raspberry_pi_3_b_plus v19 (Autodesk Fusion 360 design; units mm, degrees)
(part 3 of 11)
sketch "Sketch2" plane through (0, 0, 0) normal (0, 1, 0) x axis (1, 0, 0)
  line L1 (3.725, -2.25) -> (3.725, 1.52)
  line L2 (-5.215, -2.25) -> (3.725, -2.25)
  line L3 (-5.215, 1.52) -> (-5.215, -2.25)
  line L4 (3.325, 1.92) -> (-4.815, 1.92)
  line L5 (-0.745, 5.7) -> (-0.745, -5.7)
  line L6 (5.85, -4.7) -> (-5.015, -4.7)
  line L7 (5.85, 5.7) -> (5.85, -4.7)
  line L8 (-5.015, -4.3) -> (-5.015, -4.7)
  line L9 (-5.85, -4) -> (-5.315, -4)
  line L10 (-5.85, 5.7) -> (-5.85, -4)
  line L11 (-4.75, 5.7) -> (-5.85, 5.7)
  line L12 (-4.75, 5.55) -> (-4.75, 5.7)
  line L13 (3.1, 5.55) -> (-4.75, 5.55)
  line L14 (3.1, 5.7) -> (3.1, 5.55)
  line L15 (5.85, 5.7) -> (3.1, 5.7)
  line L16 (3.85, -4.4) -> (5.85, -4.4)
  line L17 (3.85, -4.7) -> (3.85, -4.4)
  line L18 (-5.215, -4.0172) -> (-5.215, -2.25)
  line L19 (-5.215, 5.7) -> (-5.215, 1.52)
  line L20 (-2.715, 4.55) -> (-5.215, 4.55)
  line L21 (-2.715, 5.55) -> (-2.715, 4.55)
  line L22 (3.725, 4.55) -> (3.725, 5.7)
  line L23 (1.225, 4.55) -> (3.725, 4.55)
  line L24 (1.225, 5.55) -> (1.225, 4.55)
  line L25 (4.35, 0) -> (4.35, 5)
  line L26 (4.65, 5) -> (4.65, 0)
  line L27 (4.5, 0) -> (4.5, 5)
  line L28 (5.4375, -2.85) -> (5.4375, -2.25)
  line L29 (5.2375, -2.05) -> (5.0375, -2.05)
  line L30 (4.8375, -2.25) -> (4.8375, -2.85)
  line L31 (5.0375, -3.05) -> (5.2375, -3.05)
  line L32 (3.725, 4.55) -> (3.725, 1.52)
  line L33 (-3.185, 4.9) -> (-3.185, 5.55)
  line L34 (-4.385, 4.8) -> (-3.285, 4.8)
  line L35 (-4.485, 5.55) -> (-4.485, 4.9)
  line L36 (-0.845, 4.8755) -> (-0.845, 5.55)
  line L37 (1.495, 4.9) -> (1.495, 5.55)
  line L38 (2.695, 4.8) -> (1.595, 4.8)
  line L39 (2.795, 5.55) -> (2.795, 4.9)
  arc A1 centre (3.325, 1.52) radius 0.4 between (3.725, 1.52) and (3.325, 1.92)
  arc A2 centre (-4.815, 1.52) radius 0.4 clockwise from (-5.215, 1.52) to (-4.815, 1.92)
  arc A3 centre (-5.315, -4.3) radius 0.3 clockwise from (-5.315, -4) to (-5.015, -4.3)
  arc A4 centre (4.5, 0) radius 0.15 clockwise from (4.65, 0) to (4.35, 0)
  arc A5 centre (4.5, 5) radius 0.15 clockwise from (4.35, 5) to (4.65, 5)
  circle C1 centre (3.225, 4.05) radius 0.25
  circle C2 centre (-4.715, 4.05) radius 0.25
  circle C3 centre (3.105, -4.3) radius 0.15
  circle C4 centre (2.005, -4.3) radius 0.15
  circle C5 centre (0.905, -4.3) radius 0.15
  circle C6 centre (-0.195, -4.3) radius 0.15
  circle C7 centre (-1.295, -4.3) radius 0.15
  circle C8 centre (-2.395, -4.3) radius 0.15
  circle C9 centre (-3.495, -4.3) radius 0.15
  circle C10 centre (-4.595, -4.3) radius 0.15
  circle C11 centre (3.105, -3.5) radius 0.15
  circle C12 centre (2.005, -3.5) radius 0.15
  circle C13 centre (0.905, -3.5) radius 0.15
  circle C14 centre (-0.195, -3.5) radius 0.15
  circle C15 centre (-1.295, -3.5) radius 0.15
  circle C16 centre (-2.395, -3.5) radius 0.15
  circle C17 centre (-3.495, -3.5) radius 0.15
  circle C18 centre (-4.595, -3.5) radius 0.15
  circle C19 centre (3.105, -2.7) radius 0.15
  circle C20 centre (2.005, -2.7) radius 0.15
  circle C21 centre (0.905, -2.7) radius 0.15
  circle C22 centre (-0.195, -2.7) radius 0.15
  circle C23 centre (-1.295, -2.7) radius 0.15
  circle C24 centre (-2.395, -2.7) radius 0.15
  circle C25 centre (-3.495, -2.7) radius 0.15
  circle C26 centre (-4.595, -2.7) radius 0.15
  arc A6 centre (5.2375, -2.25) radius 0.2 clockwise from (5.2375, -2.05) to (5.4375, -2.25)
  arc A7 centre (5.0375, -2.25) radius 0.2 clockwise from (4.8375, -2.25) to (5.0375, -2.05)
  arc A8 centre (5.0375, -2.85) radius 0.2 clockwise from (5.0375, -3.05) to (4.8375, -2.85)
  arc A9 centre (5.2375, -2.85) radius 0.2 clockwise from (5.4375, -2.85) to (5.2375, -3.05)
  circle C27 centre (-0.745, 4.3) radius 0.375
  arc A10 centre (-3.285, 4.9) radius 0.1 clockwise from (-3.185, 4.9) to (-3.285, 4.8)
  arc A11 centre (-4.385, 4.9) radius 0.1 clockwise from (-4.385, 4.8) to (-4.485, 4.9)
  arc A12 centre (1.595, 4.9) radius 0.1 clockwise from (1.595, 4.8) to (1.495, 4.9)
  arc A13 centre (2.695, 4.9) radius 0.1 clockwise from (2.795, 4.9) to (2.695, 4.8)
  point P11 (-0.745, -2.25)
  point P20 (-5.85, 5.7)
  point P21 (-5.85, 5.7)
  point P26 (5.85, -4.4)
  point P28 (3.85, -4.7)
  point P29 (-5.215, -4.0172)
  point P30 (-5.215, 5.7)
  point P31 (-5.215, 4.55)
  point P33 (-2.715, 5.55)
  point P34 (3.725, 5.7)
  point P37 (1.225, 5.55)
  point P1 (0, 0)
  point P43 (4.5, 0)
  point P90 (-0.745, 4.3)
  point P91 (-3.185, 5.55)
  point P98 (-4.485, 5.55)
  point P99 (-0.845, 5.55)
  point P101 (1.495, 5.55)
  point P92 (-3.185, 4.9)
  point P102 (1.495, 4.9)
  point P93 (-3.285, 4.8)
  point P104 (1.595, 4.8)
  point P95 (-4.385, 4.8)
  point P105 (2.695, 4.8)
  point P96 (-4.485, 4.9)
  point P107 (2.795, 4.9)
  point P108 (2.795, 5.55)
  point P15 (5.85, 5.7)
  point P25 (3.1, 5.7)
  point P22 (-4.75, 5.7)
  point P42 (4.5, 5)
  point P44 (3.225, 4.05)
  point P45 (-4.715, 4.05)
  point P46 (3.105, -4.3)
  vertical L1
  coincident L5 P11
  tangent A1 L4
  horizontal L2
  vertical L3
  tangent A1 L1
  tangent L4 A2
  tangent L3 A2
  equal A1 A2
  horizontal L4
  midpoint L2 P11
  tangent L8 A3
  horizontal L6
  vertical L7
  horizontal L9
  vertical L8
  vertical L10
  horizontal L13
  horizontal L11
  horizontal L15
  coincident P20 P21
  vertical L12
  vertical L14
  tangent A3 L9
  collinear L11 L15
  coincident L7 P26
  coincident L6 P28
  horizontal L16
  vertical L17
  coincident A3 P29
  perpendicular L9 L18
  coincident L11 P30
  vertical L19
  coincident L19 P31
  coincident L13 P33
  horizontal L20
  vertical L21
  coincident L15 P34
  coincident L13 P37
  vertical L22
  horizontal L23
  vertical L24
  collinear L20 L23
  symmetric L5 L21 L24
  tangent L25 A4
  tangent A4 L26
  parallel L25 L26
  tangent L26 A5
  tangent L25 A5
  vertical L27
  horizontal P1 P43
  symmetric L5 C1 C2
  coincident L5 P90
  coincident L13 P91
  tangent L33 A10
  tangent L34 A11
  coincident L13 P98
  tangent A10 L34
  tangent A11 L35
  vertical L33
  horizontal L34
  vertical L35
  equal A10 A11
  coincident L13 P99
  vertical L36
  symmetric P91 L36 P101
  symmetric P92 L36 P102
  symmetric P93 L36 P104
  symmetric A10 L36 A12
  symmetric P95 L36 P105
  symmetric P96 L36 P107
  symmetric A11 L36 A13
  symmetric P98 L36 P108
  dimension "d199" radius A1 = 0.4
  dimension "d203_1" distance P1 L2 = 2.25 (= "sdc_length / 2 - 1 mm - 2.45 mm")
  dimension "d204_1" distance L1 L3 = 8.94
  dimension "d205" distance L2 L4 = 4.17
  dimension "d206_1" distance P1 L6 = 4.7 (= "sdc_length / 2 - 1 mm")
  dimension "d207" distance L7 L10 = 11.7 (= "sdc_width - sdc_shell_thickness * 2")
  dimension "d208_1" distance P1 L10 = 5.85 (= "sdc_width / 2 - sdc_shell_thickness")
  dimension "d209_1" distance L6 L9 = 0.7
  dimension "d210_1" radius A3 = 0.3
  dimension "d212_1" distance L8 L10 = 0.835
  dimension "d213_1" distance P15 P25 = 2.75
  dimension "d214_1" distance P20 P22 = 1.1
  dimension "d215_1" distance P1 L11 = 5.7 (= "sdc_length / 2")
  dimension "d216" distance L11 L13 = 0.15 (= "sdc_shell_thickness")
  dimension "d217" distance L6 L16 = 0.3 (= "sdc_shell_thickness * 2")
  dimension "d218_1" distance L7 L17 = 2
  dimension "d219" distance L19 L21 = 2.5
  dimension "d220" distance L22 L24 = 2.5 (= "d219")
  dimension "d221" distance L13 L23 = 1
  dimension "d222" distance P42 P43 = 5
  dimension "d223_1" radius A4 = 0.15
  dimension "d224" distance P1 L27 = 4.5
  dimension "d225_1" diameter C1 = 0.5
  dimension "d226" distance L22 P44 = 0.5
  dimension "d227_1" distance L20 P45 = 0.5
  dimension "d228_1" diameter C3 = 0.3
  dimension "d229_1" distance L6 P46 = 0.4
  dimension "d236_1" distance P1 P46 = 3.105
  dimension "d237_1" diameter C27 = 0.75
  dimension "d238_1" distance L13 P90 = 1.25
  dimension "d298" distance L13 L34 = 0.75
  dimension "d299" distance L33 L35 = 1.3
  dimension "d300" radius A11 = 0.1
  dimension "d302" distance L5 L33 = 2.44
  dimension "d303" distance L5 L36 = 0.1
  dimension "d234_1" R-Pattern1-uDistance = -1.1
  dimension "d235_1" R-Pattern1-vDistance = 0.8
extrude "Extrude3" new body sketch "Sketch2" profile of A1 L1 L2 L3 L4 A2 L6 L7 L8 A3 L9 L10 L11 L12 L13 L14 L15 L16 L17 L18 L19 L20 L21 L22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 along normal blind 1.27 (= "sdc_height - sdc_shell_thickness") named "d239_1"
sketch "Sketch1" plane through (0, 0, 4.7) normal (0, 0, 1) x axis (1, 0, 0)
  line L1 (5.85, 0) -> (-5.85, 0)
  line L2 (5.85, 1.27) -> (5.85, 0)
  line L3 (3.85, 0.62) -> (5.5, 0.62)
  line L4 (-5.85, 0) -> (-5.85, 1.27)
  line L5 (-5.015, 0.42) -> (3.65, 0.42)
  line L6 (5.5, 0.62) -> (5.5, 1.27)
  line L7 (-5.64, 1.27) -> (-5.64, 0.62)
  line L8 (-5.64, 0.62) -> (-5.015, 0.62)
  line L9 (0, 2.329) -> (0, 0)
  line L10 (2.935, 0.22) -> (2.935, 0.42)
  line L11 (3.275, 0.22) -> (2.935, 0.22)
  line L12 (3.275, 0.42) -> (3.275, 0.22)
  line L13 (2.175, 0.42) -> (2.175, 0.22)
  line L14 (2.175, 0.22) -> (1.835, 0.22)
  line L15 (1.835, 0.22) -> (1.835, 0.42)
  line L16 (1.075, 0.42) -> (1.075, 0.22)
  line L17 (1.075, 0.22) -> (0.735, 0.22)
  line L18 (0.735, 0.22) -> (0.735, 0.42)
  line L19 (-0.025, 0.42) -> (-0.025, 0.22)
  line L20 (-0.025, 0.22) -> (-0.365, 0.22)
  line L21 (-0.365, 0.22) -> (-0.365, 0.42)
  line L22 (-1.125, 0.42) -> (-1.125, 0.22)
  line L23 (-1.125, 0.22) -> (-1.465, 0.22)
  line L24 (-1.465, 0.22) -> (-1.465, 0.42)
  line L25 (-2.225, 0.42) -> (-2.225, 0.22)
  line L26 (-2.225, 0.22) -> (-2.565, 0.22)
  line L27 (-2.565, 0.22) -> (-2.565, 0.42)
  line L28 (-3.325, 0.42) -> (-3.325, 0.22)
  line L29 (-3.325, 0.22) -> (-3.665, 0.22)
  line L30 (-3.665, 0.22) -> (-3.665, 0.42)
  line L31 (-4.425, 0.42) -> (-4.425, 0.22)
  line L32 (-4.425, 0.22) -> (-4.765, 0.22)
  line L33 (-4.765, 0.22) -> (-4.765, 0.42)
  line L34 (3.85, 0) -> (-5.015, 0)
  line L35 (3.85, 1.27) -> (3.85, 0)
  line L36 (-5.015, 1.27) -> (3.85, 1.27)
  line L37 (-5.015, 0) -> (-5.015, 1.27)
  line L38 (5.85, 1.27) -> (3.85, 1.27)
  line L39 (-5.015, 1.27) -> (-5.315, 1.27)
  line L40 (-5.315, 1.27) -> (-5.85, 1.27)
  line L41 (-5.1211, 0.62) -> (-5.015, 0.5139)
  arc A1 centre (3.65, 0.62) radius 0.2 between (3.65, 0.42) and (3.85, 0.62)
  point P11 (-5.85, 0)
  point P18 (-5.85, 0)
  point P8 (3.65, 0.42)
  point P15 (3.65, 0.42)
  point P3 (3.85, 0.62)
  point P12 (3.85, 0.62)
  point P2 (5.5, 0.62)
  point P4 (5.5, 0.62)
  point P14 (5.85, 0)
  point P17 (5.85, 0)
  point P10 (3.65, 0.62)
  point P1 (0, 0)
  point P20 (0, 0)
  point P22 (2.935, 0.42)
  point P25 (3.275, 0.42)
  point P26 (3.105, 0.22)
  point P9 (-5.015, 0.62)
  point P7 (-5.015, 0.42)
  point P6 (-5.64, 1.27)
  point P5 (5.5, 1.27)
  point P16 (5.85, 1.27)
  point P19 (-5.85, 1.27)
  point P64 (-5.015, 0.5139)
  point P65 (-5.1211, 0.62)
  coincident P11 P18
  coincident P8 P15
  coincident P3 P12
  coincident P2 P4
  coincident P14 P17
  vertical L2
  vertical L6
  horizontal L1
  horizontal L3
  horizontal L5
  horizontal L8
  vertical L7
  vertical L4
  tangent A1 L5
  horizontal P10 P12
  collinear L3 L8
  midpoint P1 L1
  coincident P1 P20
  vertical L9
  coincident L5 P22
  perpendicular L5 L10
  perpendicular L10 L11
  coincident L5 P25
  perpendicular L5 L12
  midpoint L11 P26
  coincident P3 L35
  coincident P9 L37
  coincident P7 L37
  coincident P6 L40
  coincident P5 L38
  coincident P16 L38
  coincident P19 L40
  coincident L37 P64
  coincident L8 P65
  dimension "d165_1" distance L2 L6 = 0.35
  dimension "d169" distance L1 L3 = 0.62
  dimension "d170_1" distance L2 L4 = 11.7 (= "sdc_width - sdc_shell_thickness * 2")
  dimension "d187" distance L10 L12 = 0.34
  dimension "d188" distance L6 L7 = 11.14
  dimension "d189" distance L9 P26 = 3.105
  dimension "d190" distance L5 L11 = 0.2
  dimension "d191" distance L5 L8 = 0.2
  dimension "d243_1" angle L8 L41 = 45
  dimension "d244_1" distance P9 L41 = 0.075
  dimension "d194" R-Pattern1-uDistance = -1.1
  dimension "d195_1" R-Pattern1-vDistance = 0
extrude "Extrude4" cut sketch "Sketch1" profile of A1 L3 L5 L6 L7 L8 L35 L36 L37 L38 L39 L40 L41 against normal blind 7.4 named "d241_1"
extrude "Extrude5" cut sketch "Sketch2" profile of A1 L4 A2 L13 L19 L20 L21 L23 L24 C1 C2 C27 L32 along normal blind 0.1 named "d245_1"
extrude "Extrude6" cut sketch "Sketch2" profile of L11 L12 L13 L14 L15 L19 L20 L21 L22 L23 L24 along normal blind 0.15 named "d247_1"
extrude "Extrude7" cut sketch "Sketch2" profile of C27 along normal blind 0.2
sketch "Sketch1" plane through (0, 0.42, 0) normal (0, 1, 0) x axis (-1, 0, 0)
  line L1 (5.015, 2.25) -> (-3.65, 2.25)
  line L2 (5.015, 4.3) -> (5.015, 2.25)
  line L3 (5.015, 4.7) -> (5.015, 4.3)
  line L4 (-3.65, 4.7) -> (5.015, 4.7)
  line L5 (-3.65, 2.25) -> (-3.65, 4.7)
  line L6 (-3.275, 3.7) -> (-3.275, 4.7)
  line L7 (-3.48, 3.7) -> (-3.275, 3.7)
  line L8 (-3.48, 2.25) -> (-3.48, 3.7)
  line L9 (-3.105, 1.8992) -> (-3.105, 4.9008)
  line L10 (-2.935, 3.7) -> (-2.935, 4.7)
  line L11 (-2.73, 3.7) -> (-2.935, 3.7)
  line L12 (-2.73, 2.25) -> (-2.73, 3.7)
  line L13 (-2.175, 3.7) -> (-2.175, 4.7)
  line L14 (-2.38, 3.7) -> (-2.175, 3.7)
  line L15 (-2.38, 2.25) -> (-2.38, 3.7)
  line L16 (-1.835, 3.7) -> (-1.835, 4.7)
  line L17 (-1.63, 3.7) -> (-1.835, 3.7)
  line L18 (-1.63, 2.25) -> (-1.63, 3.7)
  line L19 (-1.075, 3.7) -> (-1.075, 4.7)
  line L20 (-1.28, 3.7) -> (-1.075, 3.7)
  line L21 (-1.28, 2.25) -> (-1.28, 3.7)
  line L22 (-0.735, 3.7) -> (-0.735, 4.7)
  line L23 (-0.53, 3.7) -> (-0.735, 3.7)
  line L24 (-0.53, 2.25) -> (-0.53, 3.7)
  line L25 (0.025, 3.7) -> (0.025, 4.7)
  line L26 (-0.18, 3.7) -> (0.025, 3.7)
  line L27 (-0.18, 2.25) -> (-0.18, 3.7)
  line L28 (0.365, 3.7) -> (0.365, 4.7)
  line L29 (0.57, 3.7) -> (0.365, 3.7)
  line L30 (0.57, 2.25) -> (0.57, 3.7)
  line L31 (1.125, 3.7) -> (1.125, 4.7)
  line L32 (0.92, 3.7) -> (1.125, 3.7)
  line L33 (0.92, 2.25) -> (0.92, 3.7)
  line L34 (1.465, 3.7) -> (1.465, 4.7)
  line L35 (1.67, 3.7) -> (1.465, 3.7)
  line L36 (1.67, 2.25) -> (1.67, 3.7)
  line L37 (2.225, 3.7) -> (2.225, 4.7)
  line L38 (2.02, 3.7) -> (2.225, 3.7)
  line L39 (2.02, 2.25) -> (2.02, 3.7)
  line L40 (2.565, 3.7) -> (2.565, 4.7)
  line L41 (2.77, 3.7) -> (2.565, 3.7)
  line L42 (2.77, 2.25) -> (2.77, 3.7)
  line L43 (3.325, 3.7) -> (3.325, 4.7)
  line L44 (3.12, 3.7) -> (3.325, 3.7)
  line L45 (3.12, 2.25) -> (3.12, 3.7)
  line L46 (3.665, 3.7) -> (3.665, 4.7)
  line L47 (3.87, 3.7) -> (3.665, 3.7)
  line L48 (3.87, 2.25) -> (3.87, 3.7)
  line L49 (4.425, 3.7) -> (4.425, 4.7)
  line L50 (4.22, 3.7) -> (4.425, 3.7)
  line L51 (4.22, 2.25) -> (4.22, 3.7)
  line L52 (4.765, 3.7) -> (4.765, 4.7)
  line L53 (4.97, 3.7) -> (4.765, 3.7)
  line L54 (4.97, 2.25) -> (4.97, 3.7)
  line L55 (-2.935, 4.7) -> (-3.275, 4.7)
  line L56 (-2.73, 2.25) -> (-3.48, 2.25)
  line L57 (-1.63, 2.25) -> (-2.38, 2.25)
  line L58 (-1.835, 4.7) -> (-2.175, 4.7)
  circle C1 centre (3.495, 2.7) radius 0.15
  circle C2 centre (3.495, 3.5) radius 0.15
  circle C3 centre (2.395, 3.5) radius 0.15
  point P10 (-3.275, 4.7)
  point P13 (-3.48, 2.25)
  point P16 (-2.935, 4.7)
  point P11 (-3.275, 3.7)
  point P17 (-2.935, 3.7)
  point P12 (-3.48, 3.7)
  point P18 (-2.73, 3.7)
  point P19 (-2.73, 2.25)
  point P1 (0, 0)
  coincident L4 P10
  perpendicular L6 L7
  coincident L1 P13
  vertical L6
  vertical L8
  vertical L9
  symmetric P10 L9 P16
  symmetric P11 L9 P17
  symmetric P12 L9 P18
  symmetric P13 L9 P19
  dimension "d251_1" distance P1 L9 = 3.105
  dimension "d252_1" distance L6 L10 = 0.34
  dimension "d253_1" distance L8 L12 = 0.75
  dimension "d254_1" distance L4 L7 = 1
  dimension "d257" R-Pattern1-uDistance = 1.1
  dimension "d258_1" R-Pattern1-vDistance = 0
extrude "Extrude8" cut sketch "Sketch1" profile of L1 L4 C1 C2 C3 L6 L7 L8 L10 L11 L12 L13 L14 L15 L16 L17 L18 L19 L20 L21 L22 L23 L24 L25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 against normal blind 0.2 named "d259_1"
face "Face1" sketch "Sketch1"
extrude "Extrude2" add of existing geometry blind 0.2
face "EdgeFlange2" FlangeHeight 0.25 named "d266_1" FlangeAngle 55 named "d267_1" BendRadius 0.1 named "d268_1"
face "EdgeFlange3" FlangeHeight 0.5 named "d269_1" FlangeAngle 55 BendRadius 0.1
face "EdgeFlange4" FlangeHeight 3.2 FlangeAngle 5
step "Unfold1"
sketch "Sketch1" plane through (0, 0.6122, 0.0536) normal (0, 0.9962, 0.0872) x axis (1, 0, 0)
  line L1 (3.48, -2.1961) -> (2.73, -2.1961)
  line L2 (3.48, 0.9864) -> (3.48, -2.1961)
  line L3 (2.73, 0.9864) -> (3.48, 0.9864)
  line L4 (2.73, -2.1961) -> (2.73, 0.9864)
  line L5 (3.105, -0.4) -> (3.105, 0.9864)
  line L6 (3.4757, -2.0648) -> (3.275, 0.9864)
  line L7 (3.48, -3.6493) -> (3.48, -2.2048)
  line L8 (2.7343, -2.0648) -> (2.935, 0.9864)
  arc A1 centre (1.48, -2.1961) radius 2 clockwise from (3.4757, -2.0648) to (3.48, -2.1961)
  arc A2 centre (4.73, -2.1961) radius 2 clockwise from (2.73, -2.1961) to (2.7343, -2.0648)
  point P6 (3.105, 0.9864)
  point P8 (3.275, 0.9864)
  point P3 (3.48, -2.1961)
  point P10 (3.48, -2.1961)
  point P14 (2.935, 0.9864)
  point P9 (3.4757, -2.0648)
  point P15 (2.7343, -2.0648)
  point P17 (2.73, -2.1961)
  midpoint L3 P6
  vertical L5
  coincident L3 P8
  tangent L6 A1
  coincident P3 P10
  tangent A1 L7
  symmetric L5 P8 P14
  symmetric L5 P9 P15
  symmetric L5 P10 P17
  symmetric L5 A1 A2
  dimension "d274" distance P8 P14 = 0.34
  dimension "d275" radius A1 = 2
extrude "Extrude3" cut sketch "Sketch1" profile of L2 L3 L4 L6 A1 L8 A2 no distance stored
step "Refold1"
face "EdgeFlange5" FlangeHeight 1 FlangeAngle 25
face "EdgeFlange6" FlangeHeight 0.6 FlangeAngle 75
step "Unfold2"
sketch "Sketch2" plane through (0, 1.5712, -1.5712) normal (0, 0.7071, -0.7071) x axis (-1, 0, 0)
  line L1 (-3.275, -0.7573) -> (-2.935, -0.7573)
  line L2 (-3.275, -1.0504) -> (-3.275, -0.7573)
  line L3 (-2.935, -1.0504) -> (-3.275, -1.0504)
  line L4 (-2.935, -0.7573) -> (-2.935, -1.0504)
  line L5 (-3.105, -0.2989) -> (-3.105, -1.0504)
  arc A1 centre (-3.055, -0.9504) radius 0.1 clockwise from (-2.9571, -0.9709) to (-3.055, -1.0504)
  arc A2 centre (-3.9769, -0.7573) radius 1.0419 clockwise from (-2.935, -0.7573) to (-2.9571, -0.9709)
  arc A3 centre (-3.155, -0.9504) radius 0.1 clockwise from (-3.155, -1.0504) to (-3.2529, -0.9709)
  arc A4 centre (-2.2331, -0.7573) radius 1.0419 clockwise from (-3.2529, -0.9709) to (-3.275, -0.7573)
  point P6 (-3.105, -1.0504)
  point P8 (-3.055, -1.0504)
  point P2 (-2.935, -0.7573)
  point P11 (-2.935, -0.7573)
  point P14 (-3.155, -1.0504)
  point P9 (-2.9571, -0.9709)
  point P15 (-3.2529, -0.9709)
  point P17 (-3.275, -0.7573)
  midpoint L3 P6
  vertical L5
  tangent L3 A1
  coincident L3 P8
  tangent L4 A2
  coincident P2 P11
  tangent A1 A2
  symmetric L5 P8 P14
  symmetric L5 P9 P15
  symmetric L5 A1 A3
  symmetric L5 P11 P17
  symmetric L5 A2 A4
  dimension "d281" radius A1 = 0.1
  dimension "d282" distance L5 P8 = 0.05
extrude "Extrude4" cut sketch "Sketch2" profile of L2 L3 L4 A1 A2 A3 A4 no distance stored
step "Refold2"
face "Face1" sketch "Sketch1"
extrude "Extrude2" add of existing geometry blind 0.2 named "d264_1"
face "EdgeFlange2" FlangeHeight 0.25 named "d266_1" FlangeAngle 55 named "d267_1" BendRadius 0.1 named "d268_1"
face "EdgeFlange3" FlangeHeight 0.5 named "d269_1" FlangeAngle 55 named "d270_1" BendRadius 0.1 named "d271_1"
face "EdgeFlange4" FlangeHeight 3.5 named "d272_1" FlangeAngle 5 named "d273_1"
step "Unfold1"
sketch "Sketch1" plane through (0, 0.6122, 0.0536) normal (0, 0.9962, 0.0872) x axis (1, 0, 0)
  line L1 (3.48, -2.1961) -> (2.73, -2.1961)
  line L2 (3.48, 1.2864) -> (3.48, -2.1961)
  line L3 (2.73, 1.2864) -> (3.48, 1.2864)
  line L4 (2.73, -2.1961) -> (2.73, 1.2864)
  line L5 (3.105, -0.4) -> (3.105, 1.2864)
  line L6 (3.4764, -2.0765) -> (3.275, 1.2864)
  line L7 (3.48, -3.6493) -> (3.48, -2.2048)
  line L8 (2.7336, -2.0765) -> (2.935, 1.2864)
  arc A1 centre (1.48, -2.1961) radius 2 clockwise from (3.4764, -2.0765) to (3.48, -2.1961)
  arc A2 centre (4.73, -2.1961) radius 2 clockwise from (2.73, -2.1961) to (2.7336, -2.0765)
  point P6 (3.105, 1.2864)
  point P8 (3.275, 1.2864)
  point P3 (3.48, -2.1961)
  point P10 (3.48, -2.1961)
  point P14 (2.935, 1.2864)
  point P9 (3.4764, -2.0765)
  point P15 (2.7336, -2.0765)
  point P17 (2.73, -2.1961)
  midpoint L3 P6
  vertical L5
  coincident L3 P8
  tangent L6 A1
  coincident P3 P10
  tangent A1 L7
  symmetric L5 P8 P14
  symmetric L5 P9 P15
  symmetric L5 P10 P17
  symmetric L5 A1 A2
  dimension "d274_1" distance P8 P14 = 0.34
  dimension "d275_1" radius A1 = 2
extrude "Extrude3" cut sketch "Sketch1" profile of L2 L3 L4 L6 A1 L8 A2 no distance stored
step "Refold1"
face "EdgeFlange5" FlangeHeight 1 named "d277_1" FlangeAngle 25 named "d278_1"
face "EdgeFlange6" FlangeHeight 0.6 named "d279_1" FlangeAngle 75 named "d280_1"
step "Unfold2"
sketch "Sketch2" plane through (0, 1.7337, -1.7337) normal (0, 0.7071, -0.7071) x axis (-1, 0, 0)
  line L1 (-3.275, -0.9502) -> (-2.935, -0.9502)
  line L2 (-3.275, -1.2432) -> (-3.275, -0.9502)
  line L3 (-2.935, -1.2432) -> (-3.275, -1.2432)
  line L4 (-2.935, -0.9502) -> (-2.935, -1.2432)
  line L5 (-3.105, -0.2989) -> (-3.105, -1.2432)
  arc A1 centre (-3.055, -1.1432) radius 0.1 clockwise from (-2.9571, -1.1637) to (-3.055, -1.2432)
  arc A2 centre (-3.9769, -0.9502) radius 1.0419 clockwise from (-2.935, -0.9502) to (-2.9571, -1.1637)
  arc A3 centre (-3.155, -1.1432) radius 0.1 clockwise from (-3.155, -1.2432) to (-3.2529, -1.1637)
  arc A4 centre (-2.2331, -0.9502) radius 1.0419 clockwise from (-3.2529, -1.1637) to (-3.275, -0.9502)
  point P6 (-3.105, -1.2432)
  point P8 (-3.055, -1.2432)
  point P2 (-2.935, -0.9502)
  point P11 (-2.935, -0.9502)
  point P14 (-3.155, -1.2432)
  point P9 (-2.9571, -1.1637)
  point P15 (-3.2529, -1.1637)
  point P17 (-3.275, -0.9502)
  midpoint L3 P6
  vertical L5
  tangent L3 A1
  coincident L3 P8
  tangent L4 A2
  coincident P2 P11
  tangent A1 A2
  symmetric L5 P8 P14
  symmetric L5 P9 P15
  symmetric L5 A1 A3
  symmetric L5 P11 P17
  symmetric L5 A2 A4
  dimension "d281_1" radius A1 = 0.1
  dimension "d282_1" distance L5 P8 = 0.05
extrude "Extrude4" cut sketch "Sketch2" profile of L2 L3 L4 A1 A2 A3 A4 no distance stored
step "Refold2"
copy_paste "CopyPaste1"
copy_paste "CopyPaste2"
copy_paste "CopyPaste3"
copy_paste "CopyPaste4"
face "Face1" sketch "Sketch1"
extrude "Extrude2" add of existing geometry blind 0.2 named "d264_2"
face "EdgeFlange2" FlangeHeight 0.25 named "d266_2" FlangeAngle 55 named "d267_2" BendRadius 0.1 named "d268_2"
face "EdgeFlange3" FlangeHeight 0.5 named "d269_2" FlangeAngle 55 named "d270_2" BendRadius 0.1 named "d271_2"
face "EdgeFlange4" FlangeHeight 3.15 named "d272_2" FlangeAngle 5 named "d273_2"
step "Unfold1"
sketch "Sketch1" plane through (0, 0.6122, 0.0536) normal (0, 0.9962, 0.0872) x axis (1, 0, 0)
  line L1 (3.48, -2.1961) -> (2.73, -2.1961)
  line L2 (3.48, 0.9364) -> (3.48, -2.1961)
  line L3 (2.73, 0.9364) -> (3.48, 0.9364)
  line L4 (2.73, -2.1961) -> (2.73, 0.9364)
  line L5 (3.105, -0.4) -> (3.105, 0.9364)
  line L6 (3.4755, -2.0627) -> (3.275, 0.9364)
  line L7 (3.48, -3.6493) -> (3.48, -2.2048)
  line L8 (2.7345, -2.0627) -> (2.935, 0.9364)
  arc A1 centre (1.48, -2.1961) radius 2 clockwise from (3.4755, -2.0627) to (3.48, -2.1961)
  arc A2 centre (4.73, -2.1961) radius 2 clockwise from (2.73, -2.1961) to (2.7345, -2.0627)
  point P6 (3.105, 0.9364)
  point P8 (3.275, 0.9364)
  point P3 (3.48, -2.1961)
  point P10 (3.48, -2.1961)
  point P14 (2.935, 0.9364)
  point P9 (3.4755, -2.0627)
  point P15 (2.7345, -2.0627)
  point P17 (2.73, -2.1961)
  midpoint L3 P6
  vertical L5
  coincident L3 P8
  tangent L6 A1
  coincident P3 P10
  tangent A1 L7
  symmetric L5 P8 P14
  symmetric L5 P9 P15
  symmetric L5 P10 P17
  symmetric L5 A1 A2
  dimension "d274_2" distance P8 P14 = 0.34
  dimension "d275_2" radius A1 = 2
extrude "Extrude3" cut sketch "Sketch1" profile of L2 L3 L4 L6 A1 L8 A2 no distance stored
step "Refold1"
face "EdgeFlange5" FlangeHeight 1 named "d277_2" FlangeAngle 25 named "d278_2"
face "EdgeFlange6" FlangeHeight 0.6 named "d279_2" FlangeAngle 75 named "d280_2"
step "Unfold2"
sketch "Sketch2" plane through (0, 1.5441, -1.5441) normal (0, 0.7071, -0.7071) x axis (-1, 0, 0)
  line L1 (-3.275, -0.7252) -> (-2.935, -0.7252)
  line L2 (-3.275, -1.0183) -> (-3.275, -0.7252)
  line L3 (-2.935, -1.0183) -> (-3.275, -1.0183)
  line L4 (-2.935, -0.7252) -> (-2.935, -1.0183)
  line L5 (-3.105, -0.2989) -> (-3.105, -1.0183)
  arc A1 centre (-3.055, -0.9183) radius 0.1 clockwise from (-2.9571, -0.9388) to (-3.055, -1.0183)
  arc A2 centre (-3.9769, -0.7252) radius 1.0419 clockwise from (-2.935, -0.7252) to (-2.9571, -0.9388)
  arc A3 centre (-3.155, -0.9183) radius 0.1 clockwise from (-3.155, -1.0183) to (-3.2529, -0.9388)
  arc A4 centre (-2.2331, -0.7252) radius 1.0419 clockwise from (-3.2529, -0.9388) to (-3.275, -0.7252)
  point P6 (-3.105, -1.0183)
  point P8 (-3.055, -1.0183)
  point P2 (-2.935, -0.7252)
  point P11 (-2.935, -0.7252)
  point P14 (-3.155, -1.0183)
  point P9 (-2.9571, -0.9388)
  point P15 (-3.2529, -0.9388)
  point P17 (-3.275, -0.7252)
  midpoint L3 P6
  vertical L5
  tangent L3 A1
  coincident L3 P8
  tangent L4 A2
  coincident P2 P11
  tangent A1 A2
  symmetric L5 P8 P14
  symmetric L5 P9 P15
  symmetric L5 A1 A3
  symmetric L5 P11 P17
  symmetric L5 A2 A4
  dimension "d281_2" radius A1 = 0.1
  dimension "d282_2" distance L5 P8 = 0.05
extrude "Extrude4" cut sketch "Sketch2" profile of L2 L3 L4 A1 A2 A3 A4 no distance stored
step "Refold2"
position "Position1"
copy_paste "CopyPaste5"
sketch "Sketch3" plane through (0, 1.27, 0) normal (0, 1, 0) x axis (-1, 0, 0)
  line L1 (-5.5, 4.4) -> (-5.5, -2.7)
  line L2 (-5.85, 4.4) -> (-5.5, 4.4)
  line L3 (-5.85, -5.7) -> (-5.85, 4.4)
  line L4 (-3.1, -5.7) -> (-5.85, -5.7)
  line L5 (-3.1, -5.55) -> (-3.1, -5.7)
  line L6 (-2.795, -5.55) -> (-3.1, -5.55)
  line L7 (4.75, -5.7) -> (4.75, -5.55)
  line L8 (5.85, -5.7) -> (4.75, -5.7)
  line L9 (5.85, 4) -> (5.85, -5.7)
  line L10 (5.64, 4) -> (5.85, 4)
  line L11 (5.64, -2.7) -> (5.64, 4)
  line L12 (-4.35, -2.7) -> (5.64, -2.7)
  line L13 (-4.35, -5) -> (-4.35, -2.7)
  line L14 (-4.65, -2.7) -> (-4.65, -5)
  line L15 (-5.5, -2.7) -> (-4.65, -2.7)
  line L16 (-5.5, -5.2) -> (-5.5, -2.7)
  line L17 (-1.495, -5.2) -> (-5.5, -5.2)
  line L18 (-1.495, -2.7) -> (-1.495, -5.2)
  line L19 (3.185, -5.2) -> (3.185, -2.7)
  line L20 (5.64, -5.2) -> (3.185, -5.2)
  line L21 (5.64, -2.7) -> (5.64, -5.2)
  line L22 (-2.795, -4.9) -> (-2.795, -5.55)
  line L23 (-1.595, -4.8) -> (-2.695, -4.8)
  line L24 (-1.495, -5.55) -> (-1.495, -4.9)
  line L25 (3.185, -5.55) -> (-1.495, -5.55)
  line L26 (3.185, -4.9) -> (3.185, -5.55)
  line L27 (4.385, -4.8) -> (3.285, -4.8)
  line L28 (4.485, -5.55) -> (4.485, -4.9)
  line L29 (4.75, -5.55) -> (4.485, -5.55)
  arc A1 centre (-4.5, -5) radius 0.15 clockwise from (-4.35, -5) to (-4.65, -5)
  circle C1 centre (4.715, -4.05) radius 0.25
  circle C2 centre (-3.225, -4.05) radius 0.25
  arc A2 centre (-2.695, -4.9) radius 0.1 clockwise from (-2.795, -4.9) to (-2.695, -4.8)
  arc A3 centre (-1.595, -4.9) radius 0.1 clockwise from (-1.595, -4.8) to (-1.495, -4.9)
  arc A4 centre (3.285, -4.9) radius 0.1 clockwise from (3.185, -4.9) to (3.285, -4.8)
  arc A5 centre (4.385, -4.9) radius 0.1 clockwise from (4.385, -4.8) to (4.485, -4.9)
  point P2 (-5.5, -2.7)
  point P21 (-5.5, -2.7)
  point P23 (-1.495, -2.7)
  point P24 (3.185, -2.7)
  point P13 (5.64, -2.7)
  point P27 (5.64, -2.7)
  point P25 (3.185, -5.2)
  point P44 (-1.495, -5.2)
  coincident P2 P21
  horizontal L17
  vertical L16
  coincident L12 P23
  vertical L18
  coincident L12 P24
  vertical L19
  horizontal L20
  vertical L21
  coincident P13 P27
  collinear L17 L20
  coincident P25 L26
  coincident L24 P44
  dimension "d286" distance L15 L17 = 2.5
extrude "Extrude9" cut sketch "Sketch3" profile of L12 L13 A1 L14 L15 C1 C2 L16 L17 L18 L19 L20 L21 L22 A4 L27 A5 L28 against normal blind 0.65
sketch "Sketch4" plane through (5.85, 0, 0) normal (1, 0, 0) x axis (0, 0, -1)
  line L1 (5.7, 0) -> (-4.4, 0)
  line L2 (5.7, 1.27) -> (5.7, 0)
  line L3 (-4.4, 1.27) -> (5.7, 1.27)
  line L4 (-4.4, 0) -> (-4.4, 1.27)
  line L5 (3.5625, 0.82) -> (2.4375, 0.82)
  line L6 (3.5625, 0.32) -> (3.5625, 0.82)
  line L7 (2.4375, 0.32) -> (3.5625, 0.32)
  line L8 (2.4375, 0.82) -> (2.4375, 0.32)
  line L9 (2.4375, 0.57) -> (3.5625, 0.57)
  line L10 (1.625, 0.625) -> (1.625, 0)
  line L11 (1.025, 0.725) -> (1.525, 0.725)
  line L12 (0.925, 0) -> (0.925, 0.625)
  line L13 (-3.8, 0.82) -> (-4.4, 0.82)
  line L14 (-3.8, 0.32) -> (-3.8, 0.82)
  line L15 (-4.4, 0.32) -> (-3.8, 0.32)
  line L16 (-4.4, 0.82) -> (-4.4, 0.32)
  arc A1 centre (1.525, 0.625) radius 0.1 clockwise from (1.525, 0.725) to (1.625, 0.625)
  arc A2 centre (1.025, 0.625) radius 0.1 clockwise from (0.925, 0.625) to (1.025, 0.725)
  point P10 (3.5625, 0.57)
  point P11 (2.4375, 0.57)
  point P12 (3, 0.57)
  point P20 (0.925, 0)
  point P13 (1.625, 0)
  point P21 (-4.4, 0.82)
  point P25 (1.275, 0.725)
  point P1 (0, 0)
  horizontal L5
  vertical L6
  horizontal L7
  vertical L8
  midpoint L6 P10
  midpoint L8 P11
  midpoint L9 P12
  tangent L10 A1
  tangent L11 A2
  vertical L12
  coincident L1 P20
  vertical L10
  coincident L1 P13
  tangent A1 L11
  tangent A2 L12
  horizontal L11
  equal A1 A2
  horizontal L13
  vertical L14
  horizontal L15
  vertical L16
  collinear L7 L15
  collinear L5 L13
  coincident L4 P21
  midpoint L11 P25
  dimension "d304" distance L5 L7 = 0.5
  dimension "d305" distance L6 L8 = 1.125
  dimension "d306" distance L3 L9 = 0.7
  dimension "d308" distance L1 L11 = 0.725
  dimension "d309" radius A2 = 0.1
  dimension "d310" distance L10 L12 = 0.7
  dimension "d315" distance L14 L16 = 0.6
  dimension "d325" distance P1 P25 = 1.275
  dimension "d326" distance P1 P12 = 3
extrude "Extrude10" add sketch "Sketch4" profile of L1 L4 L5 L6 L7 L8 L10 A1 L11 A2 L12 L13 L14 L15 L16 along normal blind 0.15 (= "sdc_shell_thickness")
chamfer "Chamfer1" distance 0.15
sketch "Sketch5" plane through (0, 1.27, 0) normal (0, 1, 0) x axis (-1, 0, 0)
  line L1 (-5.5, -5.2) -> (-2.795, -5.2)
  line L2 (-5.5, 4.4) -> (-5.5, -5.2)
  line L3 (-5.85, 4.4) -> (-5.5, 4.4)
  line L4 (-5.85, -5.7) -> (-5.85, 4.4)
  line L5 (-3.1, -5.7) -> (-5.85, -5.7)
  line L6 (-3.1, -5.55) -> (-3.1, -5.7)
  line L7 (-2.795, -5.55) -> (-3.1, -5.55)
  line L8 (-2.795, -5.2) -> (-2.795, -5.55)
  line L9 (-5.55, 3.85) -> (-5.85, 3.85)
  line L10 (-5.55, 4.35) -> (-5.55, 3.85)
  line L11 (-5.85, 4.35) -> (-5.55, 4.35)
  line L12 (5.85, 4) -> (5.85, -5.7)
  line L13 (5.85, -5.7) -> (5.85, 4)
  line L14 (5.65, 3.95) -> (5.85, 3.95)
  line L15 (5.65, 3.45) -> (5.65, 3.95)
  line L16 (5.85, 3.45) -> (5.65, 3.45)
  line L17 (5.64, 4) -> (5.85, 4)
  point P10 (-5.85, 3.85)
  point P13 (-5.85, 4.35)
  point P18 (5.85, 3.95)
  point P21 (5.85, 3.45)
  point P5 (-5.85, 4.4)
  coincident L4 P10
  coincident L4 P13
  horizontal L11
  vertical L10
  horizontal L9
  coincident L12 P18
  coincident L12 P21
  horizontal L16
  vertical L15
  horizontal L14
  dimension "d316" distance P5 L11 = 0.05
  dimension "d317" distance L9 L11 = 0.5
  dimension "d318" distance L4 L10 = 0.3
  dimension "d320" distance L14 L17 = 0.05
  dimension "d321" distance P18 P21 = 0.5
  dimension "d322" distance L13 L15 = 0.2
extrude "Extrude11" add sketch "Sketch5" profile of L4 L9 L10 L11 L12 L13 L14 L15 L16 along normal blind 0.15 (= "sdc_shell_thickness")
work_plane "WorkPlane1" AlongDistance 0.05
sketch "Sketch1" plane through (4.4, 0, 0) normal (1, 0, 0) x axis (0, 0, -1)
  line L1 (0.4, 0.2) -> (4.06, 0.2)
  line L2 (0.4, 1.2) -> (0.4, 0.2)
  line L3 (4.9, 0.6) -> (0.9, 0.6)
  line L4 (4.9, 0.2) -> (4.9, 0.6)
  line L5 (0.9, 1.2) -> (0.4, 1.2)
  line L6 (0.9, 0.7) -> (0.9, 1.2)
  line L7 (4.06, 0.125) -> (4.4, 0.125)
  line L8 (4.06, 0.2) -> (4.06, 0.125)
  line L9 (4.4, 0.2) -> (4.9, 0.2)
  line L10 (4.4, 0.125) -> (4.4, 0.2)
  arc A1 centre (0.9, 0.65) radius 0.05 clockwise from (0.9, 0.6) to (0.9, 0.7)
  point P8 (0.9, 0.7)
  point P9 (0.9, 0.65)
  point P1 (0, 0)
  horizontal L1
  vertical L2
  horizontal L3
  vertical L4
  perpendicular L2 L5
  perpendicular L5 L6
  tangent L3 A1
  perpendicular L4 L7
  perpendicular L1 L8
  vertical P8 P9
  perpendicular L4 L9
  perpendicular L7 L10
  collinear L1 L9
  dimension "d327" distance L1 L3 = 0.4
  dimension "d328" distance L1 L7 = 0.075 (= "sdc_shell_thickness / 2")
  dimension "d329" radius A1 = 0.05
  dimension "d330" distance L5 P8 = 0.5
  dimension "d333" distance L2 L6 = 0.5
  dimension "d334" distance L2 L4 = 4.5
  dimension "d339" distance L4 L10 = 0.5
  dimension "d340" distance L8 L10 = 0.34
  dimension "d345" distance P1 L2 = 0.4
  dimension "d346" distance P1 L1 = 0.2
face "Face1" sketch "Sketch1"
face "EdgeFlange2" FlangeHeight 4 FlangeAngle 15
face "EdgeFlange3" FlangeHeight 1.2 FlangeAngle 135
face "EdgeFlange4" FlangeHeight 0.65 FlangeAngle 90 BendRadius 0.05
work_plane "WorkPlane1" AlongDistance 5 (= "sdc_width / 2 - 1 mm")
sketch "Sketch1" plane through (5, 0, 0) normal (1, 0, 0) x axis (0, 0, -1)
  line L1 (0, 1.25) -> (0, 0.25)
  line L2 (0.65, 1.25) -> (0, 1.25)
  line L3 (0.65, 0.75) -> (0.65, 1.25)
  line L4 (0.6, 0.25) -> (0.6, 0.75)
  line L5 (0.13, 0.2) -> (0.47, 0.2)
  line L6 (0.3, 0.2) -> (0.3, 1.25)
  line L7 (0.47, 0.25) -> (0.47, 0.2)
  line L8 (0.6, 0.25) -> (0.47, 0.25)
  line L9 (0.13, 0.25) -> (0.13, 0.2)
  line L10 (0, 0.25) -> (0.13, 0.25)
  line L11 (0.6, 0.75) -> (0.65, 0.75)
  point P9 (0.3, 0.2)
  point P5 (0.6, 0.75)
  point P10 (0.6, 0.75)
  point P12 (0.6, 0.25)
  point P14 (0, 0.25)
  point P3 (0.65, 1.25)
  point P4 (0.65, 0.75)
  point P1 (0, 0)
  vertical L3
  horizontal L2
  vertical L1
  horizontal L5
  vertical L4
  midpoint L5 P9
  vertical L6
  horizontal L11
  perpendicular L5 L7
  perpendicular L4 L8
  perpendicular L1 L10
  collinear L8 L10
  coincident P5 P10
  symmetric L6 P12 P14
  dimension "d349" distance P3 P4 = 0.5
  dimension "d352" distance P1 L6 = 0.3
  dimension "d353" distance P1 P9 = 0.2
  dimension "d355" distance L5 L10 = 0.05
  dimension "d356" distance L2 L10 = 1
  dimension "d357" distance L7 L9 = 0.34
  dimension "d360" distance L1 L4 = 0.6
  dimension "d361" distance L3 L4 = 0.05
face "Face1" sketch "Sketch1"
face "EdgeFlange2" FlangeHeight 4.25 FlangeAngle 5
face "EdgeFlange3" FlangeHeight 0.8 FlangeAngle 90 BendRadius 0.1 BendRemnant 0.3 EdgeWidth 0.2
work_plane "WorkPlane1" AlongDistance 15.35 named "d2_3"
canvas "Canvas1"
sketch "Sketch1" plane through (0, 0, 15.35) normal (0, 0, 1) x axis (1, 0, 0)
  line L1 (-8.5, -6.55) -> (8.5, -6.55)
  line L2 (8.5, 6.55) -> (-8.5, 6.55)
  line L3 (8.5, -6.55) -> (8.5, 6.55)
  line L4 (-8.5, 6.55) -> (8.5, -6.55)
  line L5 (8.5, 6.55) -> (-8.5, -6.55)
  line L6 (-10.1433, 0) -> (0, 0)
  line L7 (-8.425, 3.7701) -> (-8.425, -3.7701)
  line L8 (-8.5, -5.25) -> (-8.5, -6.55)
  line L9 (-8.5, -4.05) -> (-8.5, -5.05)
  line L10 (-8.5, 5.05) -> (-8.5, 4.05)
  line L11 (-8.5, 6.55) -> (-8.5, 5.25)
  line L12 (7.2048, 4.0111) -> (1.75, 4.875)
  line L13 (7.5, 2.3346) -> (7.5, 3.6654)
  line L14 (1.75, 3) -> (7.5, 3)
  line L15 (1.75, 1.125) -> (1.75, 4.875)
  line L16 (7.2048, 1.9889) -> (1.75, 1.125)
  line L17 (1.75, -1.125) -> (1.75, -4.875)
  line L18 (7.2048, -1.9889) -> (1.75, -1.125)
  line L19 (7.5, -2.3346) -> (7.5, -3.6654)
  line L20 (7.2048, -4.0111) -> (1.75, -4.875)
  arc A1 centre (-8.5, 5.15) radius 0.1 clockwise from (-8.5, 5.25) to (-8.5, 5.05)
  arc A2 centre (-8.5, 3.9) radius 0.15 clockwise from (-8.5, 4.05) to (-8.425, 3.7701)
  arc A3 centre (-8.5, -3.9) radius 0.15 clockwise from (-8.425, -3.7701) to (-8.5, -4.05)
  arc A4 centre (-8.5, -5.15) radius 0.1 clockwise from (-8.5, -5.05) to (-8.5, -5.25)
  arc A5 centre (7.15, 3.6654) radius 0.35 clockwise from (7.2048, 4.0111) to (7.5, 3.6654)
  arc A6 centre (7.15, 2.3346) radius 0.35 clockwise from (7.5, 2.3346) to (7.2048, 1.9889)
  arc A7 centre (7.15, -2.3346) radius 0.35 clockwise from (7.2048, -1.9889) to (7.5, -2.3346)
  arc A8 centre (7.15, -3.6654) radius 0.35 clockwise from (7.5, -3.6654) to (7.2048, -4.0111)
  point P6 (0, 0)
  point P1 (0, 0)
  point P7 (-8.5, 5.25)
  point P8 (-8.5, 5.05)
  point P9 (-8.5, 5.15)
  point P10 (-8.5, 4.05)
  point P11 (-8.5, 3.9)
  point P12 (0, 0)
  point P18 (-8.5, -5.25)
  point P17 (-8.5, -5.05)
  point P15 (-8.5, -4.05)
  point P23 (1.75, 3)
  point P21 (1.75, 4.875)
  point P25 (1.75, 1.125)
  point P24 (1.75, 1.125)
  point P26 (1.75, -4.875)
  point P27 (1.75, -1.125)
  point P28 (1.75, -3)
  point P22 (7.5, 3)
  point P29 (7.2048, 4.0111)
  point P33 (7.2048, 1.9889)
  point P42 (1.75, -4.875)
  point P35 (1.75, -1.125)
  point P41 (7.2048, -4.0111)
  point P30 (7.5, 3.6654)
  point P39 (7.5, -3.6654)
  point P32 (7.5, 2.3346)
  point P38 (7.5, -2.3346)
  point P36 (7.2048, -1.9889)
  point P4 (-8.5, 6.55)
  point P5 (8.5, 6.55)
  point P3 (-8.5, -6.55)
  perpendicular L1 L8
  parallel L1 L2
  parallel L3 L8
  horizontal L1
  coincident L4 P6
  coincident L5 P6
  coincident P1 P6
  coincident P7 L8
  coincident P8 L8
  coincident P9 L8
  coincident P10 L8
  coincident P11 L8
  coincident P1 P12
  horizontal L6
  symmetric P7 L6 P18
  symmetric P8 L6 P17
  symmetric A1 L6 A4
  symmetric P10 L6 P15
  symmetric A2 L6 A3
  collinear L8 L10
  collinear L8 L9
  collinear L10 L11
  vertical L7
  vertical L13
  vertical L15
  midpoint P23 L15
  symmetric P21 L14 P25
  coincident P24 P25
  symmetric L6 P21 P26
  symmetric L6 P24 P27
  midpoint L17 P28
  coincident L13 P22
  tangent L12 A5
  tangent L13 A5
  tangent L13 A6
  tangent L16 A6
  equal A5 A6
  symmetric L14 P29 P33
  symmetric L6 P21 P42
  symmetric L6 P25 P35
  symmetric L6 P29 P41
  symmetric L6 P30 P39
  symmetric L6 A5 A8
  symmetric L6 P32 P38
  symmetric L6 P33 P36
  symmetric L6 A6 A7
  dimension "d3_2" distance P4 P5 = 17
  dimension "d4_2" distance P3 P4 = 13.1
  dimension "d8_5" radius A1 = 0.1
  dimension "d10_3" distance L2 P9 = 1.4 (= "1.5 mm - 0.1 mm")
  dimension "d11_5" distance P9 P11 = 1.25
  dimension "d14_2" radius A2 = 0.15
  dimension "d15_2" distance L7 L10 = 0.075
  dimension "d46_3" distance L14 P28 = 6
  dimension "d48_3" angle L12 L15 = 81
  dimension "d49_3" distance P21 P24 = 3.75
  dimension "d52_4" distance L3 L13 = 1
  dimension "d69_4" radius A5 = 0.35
  dimension "d245_2" distance L13 L15 = 5.75
face "Face1" sketch "Sketch1"
face "EdgeFlange2" FlangeHeight 14.35 (= "13.75 mm + ( 0.3 * 2 ) * 1 mm") named "d16_3" FlangeAngle 90 named "d17_3"
face "EdgeFlange4" EdgeOffset_1 0 named "d27_3" EdgeOffset_2 -8.22 (= "-d3_2 + 10.28 mm - 1.5 mm") named "d28_3" FlangeHeight 6.5 (= "( 13.1 / 2 ) * 1 mm - 0.05 mm") named "d29_3" FlangeAngle 90 named "d30_5" EdgeOffset_1 -8.22 (= "d28_3") named "d31_5" EdgeOffset_2 0 named "d32_4" BendWidth 0.5 named "d33_4" BendDepth 0.25 named "d34_3" BendRemnant 0.6 named "d35_4"
extrude "Extrude8" cut sketch "Sketch1" profile of L12 L13 L15 L16 L17 A5 A6 L18 A7 L19 A8 L20 no distance stored
face "EdgeFlange3" EdgeOffset_1 -0.5 named "d18_4" EdgeOffset_2 -0.5 (= "d18_4") named "d19_3" EdgeOffset_1 -0.5 (= "d18_4") named "d20_3" EdgeOffset_2 -0.5 (= "d18_4") named "d21_3" FlangeHeight 0.95 (= "( ( 15 - 13.1 ) / 2 ) * 1 mm") named "d22_4" FlangeAngle 90 named "d23_4" EdgeOffset_1 -0.5 (= "d18_4") named "d24_4" EdgeOffset_2 -0.5 (= "d18_4") named "d25_4" EdgeOffset_1 0 named "d36_3" EdgeOffset_2 -0.5 (= "d18_4") named "d37_3" EdgeOffset_1 -0.5 (= "d18_4") named "d38_2" EdgeOffset_2 0 named "d39_2"
face "EdgeFlange5" FlangeHeight 0.97 (= "15.32 mm - d16_3") named "d40_2" FlangeAngle 0 named "d41_3"
face "EdgeFlange6" FlangeHeight 3 named "d42_3" FlangeAngle 30 named "d43_2"
face "EdgeFlange7" FlangeHeight 1.5 named "d44_5" FlangeAngle 70 named "d45_3"
face "EdgeFlange8" FlangeHeight 1 named "d53_4" FlangeAngle -7.5 named "d54_4" BendWidth 0.5 named "d55_3" BendDepth 0.4 named "d56_3" BendRemnant 0.6 named "d57_3"
sketch "Sketch5" plane through (0, -6.55, 0) normal (0, -1, 0) x axis (1, 0, 0)
  line L1 (-0.78, 0.1908) -> (-8.5, 0.1908)
  line L2 (-0.78, 1.6) -> (-0.78, 0.1908)
  line L3 (7.9, 1.6) -> (-0.28, 1.6)
  line L4 (7.9, 2.1) -> (7.9, 1.6)
  line L5 (7.9, 14.25) -> (7.9, 2.1)
  line L6 (7.9, 14.75) -> (7.9, 14.25)
  line L7 (-8.5, 14.75) -> (7.9, 14.75)
  line L8 (-8.5, 0.1908) -> (-8.5, 14.75)
  line L9 (-5.5966, 8.175) -> (7.9, 8.175)
  line L10 (1.8477, 5.1467) -> (6.8739, 5.675)
  line L11 (1.4, 3.7005) -> (1.4, 4.6495)
  line L12 (6.8739, 2.675) -> (1.8477, 3.2033)
  line L13 (1.4, 4.175) -> (6.9, 4.175)
  line L14 (6.9, 3.1736) -> (6.9, 5.1764)
  line L15 (1.4, 12.6495) -> (1.4, 11.7005)
  line L16 (6.8739, 13.675) -> (1.8477, 13.1467)
  line L17 (6.9, 13.1764) -> (6.9, 11.1736)
  line L18 (1.8477, 11.2033) -> (6.8739, 10.675)
  line L19 (-4.2, 11.35) -> (-2.5, 11.35)
  line L20 (-4.2, 13.05) -> (-4.2, 11.35)
  line L21 (-2.5, 13.05) -> (-4.2, 13.05)
  line L22 (-2.5, 11.35) -> (-2.5, 13.05)
  line L23 (-4.2, 13.05) -> (-2.5, 11.35)
  line L24 (-2.5, 13.05) -> (-4.2, 11.35)
  line L25 (-7.5, 7.675) -> (-6.5, 7.675)
  line L26 (-7.5, 10.675) -> (-7.5, 7.675)
  line L27 (-6.5, 10.675) -> (-7.5, 10.675)
  line L28 (-6.5, 7.675) -> (-6.5, 10.675)
  line L29 (-7.5, 10.675) -> (-6.5, 7.675)
  line L30 (-6.5, 10.675) -> (-7.5, 7.675)
  line L31 (7.9, 15.35) -> (-8.5, 15.35)
  line L32 (-4.225, 7.55) -> (3.125, 7.55)
  line L33 (-4.225, 8.8) -> (-4.225, 7.55)
  line L34 (3.125, 8.8) -> (-4.225, 8.8)
  line L35 (3.125, 7.55) -> (3.125, 8.8)
  line L36 (-4.225, 8.8) -> (3.125, 7.55)
  line L37 (3.125, 8.8) -> (-4.225, 7.55)
  line L38 (-4.2, 3.3) -> (-4.2, 5)
  line L39 (-2.5, 3.3) -> (-4.2, 3.3)
  line L40 (-2.5, 5) -> (-2.5, 3.3)
  line L41 (-4.2, 5) -> (-2.5, 5)
  line L42 (-8, 3.425) -> (-8, 4.925)
  line L43 (-8.5, 4.175) -> (-8, 4.175)
  arc A1 centre (-0.53, 1.6) radius 0.25 clockwise from (-0.78, 1.6) to (-0.28, 1.6)
  arc A2 centre (1.9, 4.6495) radius 0.5 clockwise from (1.4, 4.6495) to (1.8477, 5.1467)
  arc A3 centre (1.9, 3.7005) radius 0.5 clockwise from (1.8477, 3.2033) to (1.4, 3.7005)
  arc A4 centre (6.9, 2.9236) radius 0.25 clockwise from (6.9, 3.1736) to (6.8739, 2.675)
  arc A5 centre (6.9, 5.4264) radius 0.25 clockwise from (6.8739, 5.675) to (6.9, 5.1764)
  arc A6 centre (1.9, 12.6495) radius 0.5 clockwise from (1.4, 12.6495) to (1.8477, 13.1467)
  arc A7 centre (6.9, 13.4264) radius 0.25 clockwise from (6.8739, 13.675) to (6.9, 13.1764)
  arc A8 centre (6.9, 10.9236) radius 0.25 clockwise from (6.9, 11.1736) to (6.8739, 10.675)
  arc A9 centre (1.9, 11.7005) radius 0.5 clockwise from (1.8477, 11.2033) to (1.4, 11.7005)
  arc A10 centre (-8.25, 3.425) radius 0.25 clockwise from (-8, 3.425) to (-8.25, 3.175)
  arc A11 centre (-8.25, 2.925) radius 0.25 clockwise from (-8.5, 2.925) to (-8.25, 3.175)
  arc A12 centre (-8.25, 4.925) radius 0.25 clockwise from (-8.25, 5.175) to (-8, 4.925)
  arc A13 centre (-8.25, 5.425) radius 0.25 clockwise from (-8.25, 5.175) to (-8.5, 5.425)
  arc A14 centre (-7.35, 10.525) radius 0.15 clockwise from (-7.5, 10.525) to (-7.35, 10.675)
  arc A15 centre (-7.35, 7.825) radius 0.15 clockwise from (-7.35, 7.675) to (-7.5, 7.825)
  arc A16 centre (-6.65, 7.825) radius 0.15 clockwise from (-6.5, 7.825) to (-6.65, 7.675)
  arc A17 centre (-6.65, 10.525) radius 0.15 clockwise from (-6.65, 10.675) to (-6.5, 10.525)
  point P14 (7.9, 8.175)
  point P21 (1.4, 4.175)
  point P20 (6.9, 4.175)
  point P27 (6.9, 5.4264)
  point P26 (6.9, 2.9236)
  point P12 (6.8739, 5.675)
  point P37 (6.8739, 10.675)
  point P13 (6.8739, 2.675)
  point P32 (6.8739, 13.675)
  point P16 (1.8477, 5.1467)
  point P38 (1.8477, 11.2033)
  point P17 (1.4, 4.6495)
  point P28 (1.4, 11.7005)
  point P18 (1.4, 3.7005)
  point P29 (1.4, 12.6495)
  point P19 (1.8477, 3.2033)
  point P31 (1.8477, 13.1467)
  point P22 (6.9, 5.1764)
  point P35 (6.9, 11.1736)
  point P23 (6.9, 3.1736)
  point P34 (6.9, 13.1764)
  point P44 (-3.35, 12.2)
  point P49 (-7, 9.175)
  point P56 (-0.55, 8.175)
  point P57 (-0.3, 14.75)
  point P40 (-2.5, 11.35)
  point P61 (-2.5, 5)
  point P41 (-4.2, 11.35)
  point P58 (-4.2, 5)
  point P42 (-4.2, 13.05)
  point P59 (-4.2, 3.3)
  point P43 (-2.5, 13.05)
  point P60 (-2.5, 3.3)
  point P66 (-8.5, 2.925)
  point P70 (-8.5, 5.425)
  point P72 (-8, 4.175)
  point P73 (-8.5, 4.175)
  point P69 (-8.25, 4.925)
  point P71 (-8.25, 5.425)
  point P75 (-7.35, 10.675)
  point P74 (-7.5, 10.525)
  point P78 (-7.35, 7.675)
  point P77 (-7.5, 7.825)
  point P81 (-6.5, 7.825)
  point P80 (-6.65, 7.675)
  point P84 (-6.65, 10.675)
  point P83 (-6.5, 10.525)
  point P46 (-7.5, 7.675)
  point P47 (-7.5, 10.675)
  point P48 (-6.5, 10.675)
  point P54 (-4.225, 8.8)
  point P55 (3.125, 8.8)
  point P53 (-4.225, 7.55)
  point P62 (-8, 4.925)
  point P63 (-8, 3.425)
  midpoint L5 P14
  horizontal L9
  midpoint L11 P21
  horizontal L13
  vertical L14
  midpoint P20 L14
  tangent L11 A2
  tangent L11 A3
  tangent L10 A2
  tangent L12 A3
  tangent L12 A4
  tangent L10 A5
  vertical L11
  equal A2 A3
  coincident L14 P27
  coincident L14 P26
  equal A4 A5
  symmetric P12 L9 P37
  symmetric P13 L9 P32
  symmetric L9 P16 P38
  symmetric L9 P17 P28
  symmetric L9 P18 P29
  symmetric L9 P19 P31
  symmetric L9 P22 P35
  symmetric L9 P23 P34
  symmetric L9 A2 A9
  symmetric L9 A3 A6
  symmetric L9 A4 A7
  symmetric L9 A5 A8
  perpendicular L19 L20
  parallel L19 L21
  parallel L20 L22
  horizontal L19
  coincident L23 P44
  coincident L24 P44
  perpendicular L25 L26
  parallel L25 L27
  parallel L26 L28
  horizontal L25
  coincident L29 P49
  coincident L30 P49
  perpendicular L32 L33
  parallel L32 L34
  parallel L33 L35
  horizontal L32
  coincident L36 P56
  coincident L37 P56
  coincident L9 P56
  midpoint L7 P57
  symmetric L9 P40 P61
  symmetric L9 P41 P58
  symmetric L9 P42 P59
  symmetric L9 P43 P60
  tangent L42 A10
  coincident L8 P66
  tangent A10 A11
  vertical L42
  tangent L42 A12
  coincident L8 P70
  tangent A12 A13
  tangent L8 A13
  tangent L8 A11
  midpoint L42 P72
  coincident L8 P73
  horizontal L43
  equal A12 A13
  equal A10 A12
  equal A10 A11
  vertical P69 P71
  tangent L27 A14
  coincident L27 P75
  coincident L26 P74
  tangent L25 A15
  coincident L25 P78
  coincident L26 P77
  tangent L28 A16
  coincident L28 P81
  coincident L25 P80
  tangent L28 A17
  coincident L27 P84
  coincident L28 P83
  tangent L27 A17
  tangent L26 A14
  tangent L26 A15
  tangent L25 A16
  equal A14 A17
  equal A16 A17
  equal A15 A16
  dimension "d120_1" distance P12 P13 = 3
  dimension "d123_1" distance L9 L13 = 4
  dimension "d124_2" radius A2 = 0.5
  dimension "d125_2" radius A4 = 0.25
  dimension "d126_2" angle L10 L14 = 84
  dimension "d127_2" distance L11 L14 = 5.5
  dimension "d128_2" distance L5 L14 = 1
  dimension "d176_1" distance P42 P43 = 1.7 (= "2 mm - d1_3")
  dimension "d177_1" distance P41 P42 = 1.7
  dimension "d178_1" distance P46 P47 = 3
  dimension "d179_1" distance P47 P48 = 1
  dimension "d180_1" distance L8 L20 = 4.3 (= "4 mm + d1_3")
  dimension "d181_1" distance L8 L26 = 1
  dimension "d182_1" distance L21 L31 = 2.3 (= "2 mm + d1_3")
  dimension "d183_1" distance P54 P55 = 7.35
  dimension "d184_1" distance P53 P54 = 1.25
  dimension "d185" distance P56 P57 = 0.25
  dimension "d187_1" distance P62 P63 = 1.5
  dimension "d189_1" distance L8 L42 = 0.5
  dimension "d190_1" distance L9 L43 = 4
  dimension "d198" radius A17 = 0.15 (= "d1_3 / 2")
  dimension "d223_2" distance L9 P49 = 1
extrude "Extrude7" cut sketch "Sketch5" profile of L8 L10 L11 L12 L14 A2 A3 A4 A5 L15 A6 L16 A7 L17 A8 L18 A9 L19 L20 L21 L22 L25 L26 L27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 no distance stored
face "EdgeFlange11" FlangeHeight 3.6 named "d130_2" FlangeAngle 10 named "d131_2"
step "Unfold1"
